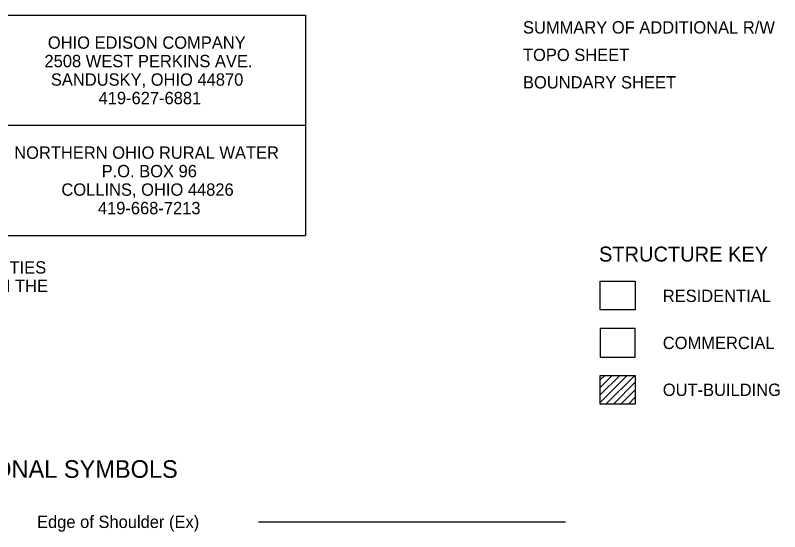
# Model space of a CAD drawing. Extents: x 0 to 34, y 0 to 22.
# Drawn here: x 7.93 to 16.61, y 5.83 to 11.7 of the extents above; entities that cross this region are included whole.
import ezdxf

# ---------------------------------------------------------------- set-up
doc = ezdxf.new("R2010")
doc.units = 0
for name, color, linetype in [('Default', 7, 'Continuous'), ('SC_Shading1', 7, 'Continuous'), ('SH_Data', 7, 'Continuous'), ('SH_Text', 7, 'Continuous')]:
    doc.layers.add(name, color=color, linetype=linetype)

msp = doc.modelspace()

# ---------------------------------------------------------------- linework, layer by layer
at = {"layer": 'Default'}
for p, q in [((6.9182, 11.698), (11.2239, 11.698)), ((6.9182, 11.698), (11.2239, 11.698)), ((11.2239, 11.698), (11.2239, 10.448)), ((6.9182, 10.448), (11.2239, 10.448)), ((6.9182, 10.448), (11.2239, 10.448)), ((11.2239, 10.448), (11.2239, 9.198)), ((6.9182, 9.198), (11.2239, 9.198))]:
    msp.add_line(p, q, dxfattribs=at)
at = {"layer": 'SC_Shading1'}
msp.add_lwpolyline([(14.5702, 7.8159), (14.9673, 7.8159), (14.9673, 8.1417), (14.5702, 8.1417)], close=True, dxfattribs=at)
at = {"layer": 'SH_Text'}
for p, q in [((14.5702, 7.6051), (14.5715, 7.6065)), ((14.5702, 7.5551), (14.6216, 7.6065)), ((14.5702, 7.4703), (14.7064, 7.6065)), ((14.5702, 7.3856), (14.791, 7.6065)), ((14.5702, 7.3009), (14.8758, 7.6065)), ((14.6345, 7.2806), (14.9605, 7.6065)), ((14.7193, 7.2806), (14.9673, 7.5286)), ((14.804, 7.2806), (14.9673, 7.4439)), ((14.8887, 7.2806), (14.9673, 7.3591)), ((14.5702, 7.2851), (14.5748, 7.2806)), ((10.6907, 5.9437), (14.1741, 5.9437))]:
    msp.add_line(p, q, dxfattribs=at)
for points in [[(14.5702, 8.6771), (14.9673, 8.6771), (14.9673, 8.3512), (14.5702, 8.3512)], [(14.5702, 7.6065), (14.9673, 7.6065), (14.9673, 7.2806), (14.5702, 7.2806)]]:
    msp.add_lwpolyline(points, close=True, dxfattribs=at)

# ---------------------------------------------------------------- texts
at = {"layer": 'Default'}
for s, p in [('OHIO EDISON COMPANY', (8.2969, 11.318)), ('2508 WEST PERKINS AVE.', (8.2588, 11.108)), ('SANDUSKY, OHIO 44870', (8.3315, 10.898)), ('419-627-6881', (8.8727, 10.688)), ('NORTHERN OHIO RURAL WATER', (7.9152, 10.068)), ('P.O. BOX 96', (8.9075, 9.858)), ('COLLINS, OHIO 44826', (8.451, 9.648)), ('419-668-7213', (8.865, 9.438))]:
    msp.add_text(s, height=0.14, dxfattribs=at).set_placement(p)
at = {"layer": 'SH_Data'}
for s, p in [('SUMMARY OF ADDITIONAL R/W          ', (13.6919, 11.4906)), ('TOPO SHEET                         ', (13.6919, 11.1786)), ('BOUNDARY SHEET                     ', (13.6919, 10.8666))]:
    msp.add_text(s, height=0.14, dxfattribs=at).set_placement(p)
at = {"layer": 'SH_Text'}
for s, height, p in [('STRUCTURE KEY', 0.17, (14.5549, 8.9006)), ('THE LOCATION OF THE UNDERGROUND UTILITIES', 0.14, (3.6809, 8.7638)), ('SHOWN ON THE PLANS ARE OBTAINED FROM THE', 0.14, (3.6809, 8.5538)), ('RESIDENTIAL', 0.14, (15.2792, 8.4409)), ('COMMERCIAL', 0.14, (15.2792, 7.9066)), ('OUT-BUILDING', 0.14, (15.2792, 7.3739)), ('CONVENTIONAL SYMBOLS', 0.2, (6.2945, 6.4437)), ('Edge of Shoulder (Ex)', 0.14, (8.1741, 5.8737))]:
    msp.add_text(s, height=height, dxfattribs=at).set_placement(p)

doc.saveas('drawing.dxf')
